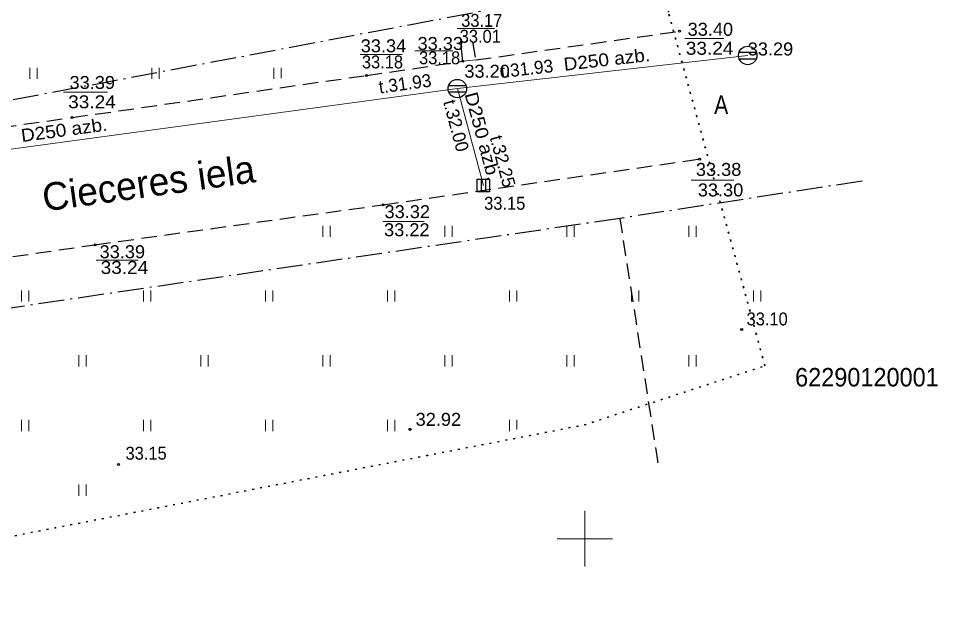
# Model space of a CAD drawing. Extents: x 380758 to 381729, y 283236 to 283533.
# Drawn here: x 381619.35 to 381669.08, y 283346.76 to 283378.15 of the extents above; entities that cross this region are included whole.
import ezdxf
from ezdxf.enums import TextEntityAlignment as Align

# ---------------------------------------------------------------- set-up
doc = ezdxf.new("R2010")
doc.units = 0
doc.header["$LTSCALE"] = 0.28
for name, pattern in [('DOT_DASHED', [7.7, 5, -1.2, 0.3, -1.2]), ('DOTTED', [1.5, 0.3, -1.2]), ('MEDIUM_DASHED', [4.5, 3, -1.5])]:
    doc.linetypes.add(name, pattern=pattern)
for name, color, linetype, lineweight in [('11', 7, 'Continuous', 13), ('23', 7, 'Continuous', 13), ('25', 7, 'DOTTED', 35), ('29', 7, 'DOT_DASHED', 25), ('30', 7, 'Continuous', 13), ('37', 7, 'MEDIUM_DASHED', 13), ('48', 7, 'Continuous', 25), ('58', 7, 'Continuous', 25)]:
    doc.layers.add(name, color=color, linetype=linetype, lineweight=lineweight)
doc.layers.add('56', color=7, linetype='Continuous')
doc.layers.add('59', color=7, linetype='Continuous')

msp = doc.modelspace()

# ---------------------------------------------------------------- linework, layer by layer
at = {"layer": '11'}
msp.add_line((381643.098, 283374.353), (381644.506, 283369.106), dxfattribs=at)
msp.add_lwpolyline([(381605.115, 283369.197), (381643.098, 283374.353), (381658.808, 283376.147)], dxfattribs=at)
at = {"layer": '23'}
for p, q in [((381619.967, 283374.882), (381619.967, 283375.482)), ((381620.367, 283374.882), (381620.367, 283375.482)), ((381626.567, 283374.882), (381626.567, 283375.482)), ((381626.967, 283374.882), (381626.967, 283375.482)), ((381633.167, 283374.882), (381633.167, 283375.482)), ((381633.567, 283374.919), (381633.567, 283375.482)), ((381635.813, 283366.325), (381635.813, 283366.925)), ((381636.213, 283366.325), (381636.213, 283366.925)), ((381642.413, 283366.325), (381642.413, 283366.925)), ((381642.813, 283366.325), (381642.813, 283366.925)), ((381649.013, 283366.325), (381649.013, 283366.925)), ((381649.413, 283366.325), (381649.413, 283366.925)), ((381655.613, 283366.325), (381655.613, 283366.925)), ((381656.013, 283366.325), (381656.013, 283366.925)), ((381619.513, 283362.825), (381619.513, 283363.425)), ((381619.913, 283362.825), (381619.913, 283363.425)), ((381626.113, 283362.825), (381626.113, 283363.425)), ((381626.513, 283362.825), (381626.513, 283363.425)), ((381632.713, 283362.825), (381632.713, 283363.425)), ((381633.113, 283362.825), (381633.113, 283363.425)), ((381639.313, 283362.825), (381639.313, 283363.425)), ((381639.713, 283362.825), (381639.713, 283363.425)), ((381645.913, 283362.825), (381645.913, 283363.425)), ((381646.313, 283362.825), (381646.313, 283363.425)), ((381652.513, 283362.825), (381652.513, 283363.425)), ((381652.913, 283362.825), (381652.913, 283363.425)), ((381659.113, 283362.825), (381659.113, 283363.425)), ((381659.513, 283362.825), (381659.513, 283363.425)), ((381622.613, 283359.325), (381622.613, 283359.925)), ((381623.013, 283359.325), (381623.013, 283359.925)), ((381629.213, 283359.325), (381629.213, 283359.925)), ((381629.613, 283359.325), (381629.613, 283359.925)), ((381635.813, 283359.325), (381635.813, 283359.925)), ((381636.213, 283359.325), (381636.213, 283359.925)), ((381642.413, 283359.325), (381642.413, 283359.925)), ((381642.813, 283359.325), (381642.813, 283359.925)), ((381649.013, 283359.325), (381649.013, 283359.925)), ((381649.413, 283359.325), (381649.413, 283359.925)), ((381655.613, 283359.325), (381655.613, 283359.925)), ((381656.013, 283359.325), (381656.013, 283359.925)), ((381619.513, 283355.825), (381619.513, 283356.425)), ((381619.913, 283355.825), (381619.913, 283356.425)), ((381626.113, 283355.825), (381626.113, 283356.425)), ((381626.513, 283355.825), (381626.513, 283356.425)), ((381632.713, 283355.825), (381632.713, 283356.425)), ((381633.113, 283355.825), (381633.113, 283356.425)), ((381639.313, 283355.825), (381639.313, 283356.425)), ((381639.713, 283355.825), (381639.713, 283356.425)), ((381645.913, 283355.825), (381645.913, 283356.425)), ((381646.313, 283355.899), (381646.313, 283356.425)), ((381622.613, 283352.325), (381622.613, 283352.925)), ((381623.013, 283352.325), (381623.013, 283352.925))]:
    msp.add_line(p, q, dxfattribs=at)
at = {"layer": '25'}
msp.add_lwpolyline([(381572.085, 283346.757), (381611.455, 283348.662), (381649.963, 283356.155), (381659.737, 283359.354), (381654.512, 283378.485), (381656.478, 283407.485), (381656.785, 283411.384)], dxfattribs=at)
at = {"layer": '29'}
for p, q in [((381646.05, 283378.842), (381617.917, 283373.524)), ((381664.994, 283369.348), (381651.906, 283367.333))]:
    msp.add_line(p, q, dxfattribs=at)
at = {"layer": '29', "linetype": 'MEDIUM_DASHED'}
msp.add_line((381653.964, 283354.105), (381651.906, 283367.333), dxfattribs=at)
at = {"layer": '29'}
msp.add_lwpolyline([(381651.906, 283367.333), (381581.444, 283356.963), (381541.971, 283356.053), (381537.716, 283357.266)], dxfattribs=at)
at = {"layer": '30'}
for points in [[(381650, 283351.5), (381650, 283350), (381650, 283348.5)], [(381648.5, 283350), (381650, 283350), (381651.5, 283350)]]:
    msp.add_lwpolyline(points, dxfattribs=at)
at = {"layer": '37'}
msp.add_line((381643.4, 283375.831), (381644.088, 283375.904), dxfattribs=at)
at = {"layer": '37', "lineweight": 25}
for points in [[(381643.924, 283376.888), (381644.088, 283375.904), (381655.116, 283377.458)], [(381605.917, 283370.502), (381622.261, 283372.788), (381638.178, 283375.067), (381643.4, 283375.831), (381643.276, 283376.813)], [(381610.31, 283364.013), (381623.505, 283365.907), (381639.084, 283368.07), (381656.206, 283370.541)]]:
    msp.add_lwpolyline(points, dxfattribs=at)
at = {"layer": '48'}
for p, q in [((381658.34, 283376.322), (381659.276, 283376.322)), ((381658.34, 283375.972), (381659.276, 283375.972)), ((381642.63, 283374.528), (381643.566, 283374.528)), ((381642.63, 283374.178), (381643.566, 283374.178)), ((381644.393, 283369.444), (381644.393, 283368.769)), ((381644.618, 283369.444), (381644.618, 283368.769))]:
    msp.add_line(p, q, dxfattribs=at)
msp.add_lwpolyline([(381644.168, 283369.444), (381644.843, 283369.444), (381644.843, 283368.769), (381644.168, 283368.769)], close=True, dxfattribs=at)
for centre in [(381658.808, 283376.147), (381643.098, 283374.353)]:
    msp.add_circle(centre, 0.5, dxfattribs=at)
at = {"layer": '58', "lineweight": 13}
for p, q in [((381643.094, 283377.602), (381645.101, 283377.602)), ((381655.405, 283377.063), (381657.51, 283377.063)), ((381640.794, 283376.402), (381642.85, 283376.402)), ((381637.832, 283376.206), (381640.108, 283376.206)), ((381621.787, 283374.154), (381624.161, 283374.154)), ((381655.748, 283369.397), (381658.049, 283369.397)), ((381639.056, 283367.169), (381641.308, 283367.169)), ((381623.549, 283365.067), (381625.825, 283365.067))]:
    msp.add_line(p, q, dxfattribs=at)
at = {"layer": '58'}
for centre in [(381655.116, 283377.4581), (381643.276, 283376.8131), (381643.4, 283375.8311), (381638.178, 283375.0671), (381622.261, 283372.7881), (381656.206, 283370.5411), (381639.084, 283368.0701), (381623.505, 283365.9071), (381658.48, 283361.3121), (381640.536, 283355.9161), (381624.764, 283354.0091)]:
    msp.add_circle(centre, 0.0534, dxfattribs=at)

# ---------------------------------------------------------------- texts
at = {"layer": '11'}
for rotation, width, p in [(6.515, 1.1, (381651.2223, 283375.5832)), (285.021, 1.15, (381644.1236, 283371.6872)), (7.73, 1.1, (381621.8664, 283371.7737))]:
    msp.add_text('D250 azb.', height=0.7, rotation=rotation, dxfattribs=dict(at, width=width)).set_placement(p, align=Align.CENTER)
for s, rotation, p in [('t.31.93', 6.515, (381646.8938, 283375.0876)), ('t.31.93', 7.73, (381640.3124, 283374.2773)), ('t.32.00', 285.021, (381642.6926, 283372.2582)), ('t.32.25', 285.021, (381645.2151, 283370.3292))]:
    msp.add_text(s, height=0.7, rotation=rotation, dxfattribs=at).set_placement(p, align=Align.CENTER)
at = {"layer": '37', "width": 0.85}
msp.add_text('A', height=1, dxfattribs=at).set_placement((381657.3715, 283372.984), align=Align.CENTER)
at = {"layer": '48'}
for s, width, p in [('33.29', 1.05, (381658.808, 283376.147)), ('33.20', 1.05, (381643.477, 283374.943)), ('33.15', 0.95, (381644.548, 283367.798))]:
    msp.add_text(s, height=0.7, dxfattribs=dict(at, width=width)).set_placement(p)
at = {"layer": '56'}
msp.add_text('Cieceres iela', height=1.5, rotation=7.904, dxfattribs=at).set_placement((381620.75, 283367.703))
at = {"layer": '58'}
for s, width, p in [('33.17', 0.95, (381643.304, 283377.695)), ('33.40', 1.05, (381655.556, 283377.213)), ('33.01', 0.95, (381643.225, 283376.834)), ('33.34', 1.05, (381637.869, 283376.32)), ('33.33', 1.05, (381640.944, 283376.445)), ('33.24', 1.1, (381655.457, 283376.185)), ('33.18', 0.95, (381641.025, 283375.67)), ('33.18', 0.95, (381637.932, 283375.445)), ('33.39', 1.05, (381622.115, 283374.335)), ('33.24', 1.1, (381622.04, 283373.289)), ('33.38', 1.05, (381656.002, 283369.629)), ('33.30', 1.05, (381656.107, 283368.519)), ('33.32', 1.05, (381639.157, 283367.343)), ('33.22', 1.05, (381639.132, 283366.366)), ('33.39', 1.05, (381623.74, 283365.177)), ('33.24', 1.1, (381623.797, 283364.326)), ('33.10', 0.95, (381658.746, 283361.54)), ('32.92', 1.05, (381640.84, 283356.106)), ('33.15', 0.95, (381625.144, 283354.275))]:
    msp.add_text(s, height=0.7, dxfattribs=dict(at, width=width)).set_placement(p)
at = {"layer": '59', "width": 0.95}
msp.add_text('62290120001', height=1, dxfattribs=at).set_placement((381661.372, 283358.236))

doc.saveas('drawing.dxf')
